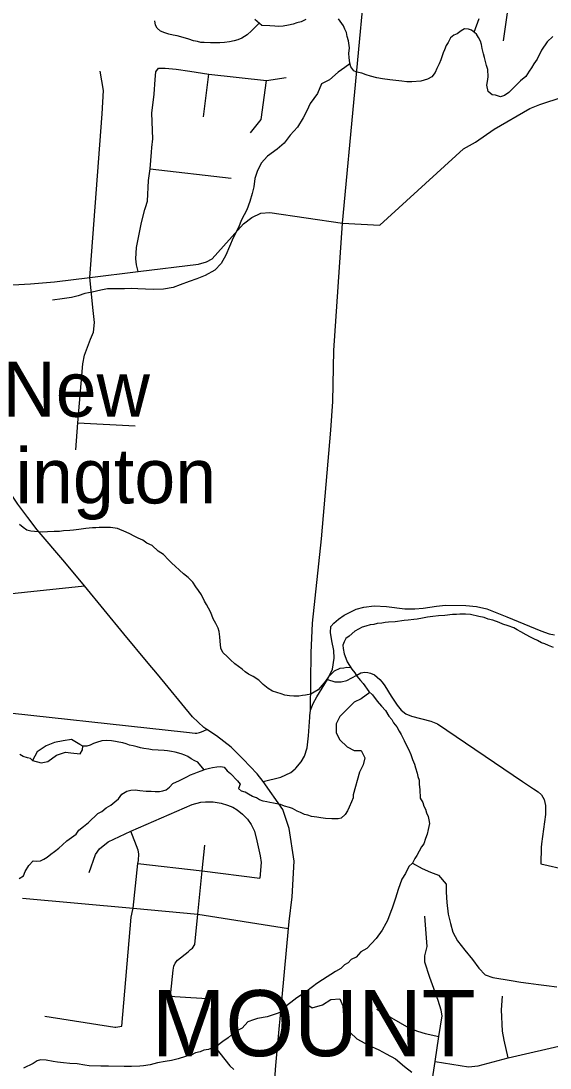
# Model space of a CAD drawing. Extents: x 0 to 34, y 0 to 22.
# Drawn here: x 6.214 to 6.973, y 17.057 to 18.558 of the extents above; entities that cross this region are included whole.
import ezdxf

# ---------------------------------------------------------------- set-up
doc = ezdxf.new("R2010")
doc.units = 0
for name, color, linetype in [('GM_X_Corporation_Text', 7, 'Continuous'), ('GM_X_County_Road', 7, 'Continuous'), ('GM_X_Minor_Lake', 7, 'Continuous'), ('GM_X_Minor_River', 7, 'Continuous'), ('GM_X_Township_Subdivision', 7, 'Continuous'), ('GM_X_Unincorporated_Text', 7, 'Continuous'), ('GM_X_US_Route', 7, 'Continuous')]:
    doc.layers.add(name, color=color, linetype=linetype)

msp = doc.modelspace()

# ---------------------------------------------------------------- linework, layer by layer
at = {"layer": 'GM_X_County_Road'}
for points in [[(6.6289, 17.5702), (6.6299, 17.6523), (6.6319, 17.6948), (6.6451, 17.8156), (6.6585, 17.9713), (6.6613, 18.0126), (6.6624, 18.0856), (6.6748, 18.2683), (6.7103, 18.6453), (6.7239, 18.8027), (6.734, 18.8917), (6.7405, 19.0079)], [(6.6748, 18.2683), (6.7285, 18.2655), (6.8486, 18.3747), (6.8655, 18.3843), (6.8923, 18.4031), (6.9436, 18.4327), (6.9578, 18.4383), (6.9913, 18.4492), (7.0954, 18.4834), (7.0971, 18.484)], [(6.063, 18.1333), (6.1136, 18.1511), (6.1283, 18.1584), (6.17, 18.1715), (6.2024, 18.1796), (6.2275, 18.1814), (6.2621, 18.1839), (6.3129, 18.1902), (6.3819, 18.1988), (6.4683, 18.2096), (6.4798, 18.2126), (6.4879, 18.217), (6.533, 18.2673), (6.545, 18.2764), (6.5577, 18.2825), (6.5706, 18.2836), (6.6748, 18.2683)], [(6.6282, 17.5603), (6.6283, 17.5621), (6.6289, 17.5702), (6.633, 17.5796), (6.6382, 17.5893), (6.6534, 17.6142), (6.6608, 17.6291), (6.663, 17.6446), (6.6626, 17.6559), (6.6596, 17.6696), (6.6576, 17.6814), (6.6584, 17.6899), (6.6626, 17.695), (6.6695, 17.7008), (6.6773, 17.7062), (6.6946, 17.7151), (6.7055, 17.7177), (6.7206, 17.7197), (6.738, 17.7187), (6.7642, 17.7153), (6.7787, 17.7154), (6.7909, 17.7162), (6.81, 17.7191), (6.8227, 17.7208), (6.8517, 17.7202), (6.8672, 17.7188), (6.8821, 17.7156), (6.8941, 17.7107), (6.9106, 17.7038), (6.9593, 17.6839), (6.9714, 17.6796), (6.9791, 17.6783)], [(5.5312, 17.5084), (5.5691, 17.507), (5.6976, 17.4979), (5.7449, 17.494), (5.7812, 17.4914), (5.8077, 17.4899), (5.8238, 17.4905), (5.8392, 17.4936), (5.8617, 17.5004), (5.9034, 17.5131), (5.9959, 17.5435), (6.0061, 17.5479), (6.0184, 17.5562), (6.041, 17.5742), (6.0478, 17.5777), (6.0541, 17.5801), (6.0612, 17.5813), (6.0695, 17.5816), (6.1446, 17.5721), (6.4513, 17.5386)], [(6.607, 17.486), (6.6073, 17.4862), (6.6082, 17.4869), (6.6157, 17.4962), (6.6204, 17.504), (6.6242, 17.5161), (6.6263, 17.5335), (6.6282, 17.5603)], [(6.4513, 17.5386), (6.4638, 17.5372), (6.4661, 17.5373), (6.47, 17.538), (6.4727, 17.5389), (6.4763, 17.5404), (6.4804, 17.5426)], [(6.5612, 17.4679), (6.5866, 17.4743), (6.6008, 17.481), (6.607, 17.486)]]:
    msp.add_lwpolyline(points, dxfattribs=at)
at = {"layer": 'GM_X_Minor_Lake'}
for points in [[(6.3028, 17.5185), (6.2984, 17.5211), (6.2864, 17.5282), (6.2746, 17.5262), (6.262, 17.5238), (6.2501, 17.5191), (6.237, 17.5106), (6.2303, 17.4982), (6.2428, 17.4945), (6.2523, 17.4966), (6.2651, 17.5058)], [(6.2651, 17.5058), (6.2777, 17.5098), (6.2857, 17.5092), (6.2989, 17.5074), (6.3021, 17.5134), (6.3028, 17.5185)]]:
    msp.add_lwpolyline(points, dxfattribs=at)
at = {"layer": 'GM_X_Minor_River'}
for points in [[(6.5554, 18.5548), (6.5443, 18.5441), (6.5385, 18.5381), (6.5308, 18.5333), (6.5251, 18.5311), (6.5197, 18.5294), (6.5132, 18.5283), (6.506, 18.5273), (6.4992, 18.5267), (6.4946, 18.5268), (6.4859, 18.5266), (6.4768, 18.5272), (6.4718, 18.5273), (6.4669, 18.5285), (6.4613, 18.5298), (6.4549, 18.5318), (6.45, 18.5334), (6.4379, 18.5367), (6.4322, 18.5376), (6.4258, 18.5392), (6.4201, 18.5412), (6.4141, 18.5433), (6.4092, 18.5475), (6.4071, 18.5521), (6.4057, 18.5583)], [(6.6224, 18.56), (6.6155, 18.5567), (6.6094, 18.5553), (6.6045, 18.5535), (6.5976, 18.5521), (6.59, 18.5508), (6.5835, 18.5501), (6.5782, 18.5506), (6.5706, 18.5512), (6.5593, 18.5514), (6.5492, 18.5603)], [(6.8077, 18.4844), (6.803, 18.478), (6.7968, 18.4744), (6.7873, 18.4719), (6.7744, 18.471), (6.7672, 18.4708), (6.7603, 18.4717), (6.7513, 18.4726), (6.7429, 18.4735), (6.7323, 18.4749), (6.724, 18.4766), (6.7153, 18.4787), (6.7089, 18.4807), (6.7025, 18.4831), (6.6957, 18.4848), (6.6912, 18.4867), (6.6871, 18.4925), (6.6853, 18.4975), (6.6844, 18.5059), (6.6841, 18.5112), (6.685, 18.5196), (6.6837, 18.5295), (6.6816, 18.5356), (6.6805, 18.5417), (6.6784, 18.5463), (6.6762, 18.5513), (6.6692, 18.561)], [(6.8636, 18.5422), (6.8711, 18.5615)], [(6.9765, 18.5358), (6.9684, 18.528), (6.9602, 18.516), (6.9542, 18.5032), (6.9495, 18.4968), (6.946, 18.4911), (6.9425, 18.4859), (6.9378, 18.4784), (6.9304, 18.4724), (6.9219, 18.4642), (6.9134, 18.4553), (6.9072, 18.4512), (6.9015, 18.4491), (6.8943, 18.4515), (6.8898, 18.4523), (6.8838, 18.457), (6.8821, 18.4658), (6.8829, 18.4711), (6.8838, 18.4779), (6.8833, 18.4886), (6.8815, 18.4943), (6.8787, 18.5058), (6.8773, 18.5108), (6.8752, 18.5184), (6.8742, 18.5242), (6.8727, 18.5291), (6.8698, 18.5345), (6.8672, 18.5391), (6.8601, 18.545), (6.8556, 18.5462), (6.8499, 18.5467), (6.8453, 18.5438), (6.8392, 18.5397), (6.8346, 18.5375), (6.8299, 18.5338), (6.8264, 18.5274), (6.8236, 18.5229), (6.8212, 18.5169), (6.8192, 18.5123), (6.816, 18.5025), (6.8136, 18.4968), (6.8104, 18.4897), (6.8077, 18.4844)], [(6.6856, 18.4968), (6.6785, 18.4915), (6.6689, 18.4845), (6.6565, 18.4737), (6.645, 18.4678), (6.639, 18.4543), (6.6288, 18.4397), (6.6237, 18.4291), (6.6185, 18.419), (6.6103, 18.4059), (6.6002, 18.3943), (6.5916, 18.3827), (6.5812, 18.3745), (6.5676, 18.3642), (6.5583, 18.3541), (6.5528, 18.3424), (6.5491, 18.3322), (6.5481, 18.3205), (6.5456, 18.3107), (6.542, 18.2993), (6.5379, 18.2873), (6.5304, 18.273), (6.526, 18.262), (6.5181, 18.247), (6.5129, 18.2349), (6.5077, 18.2225), (6.501, 18.2105), (6.4921, 18.2008), (6.4779, 18.1931), (6.466, 18.1884), (6.4553, 18.1844), (6.4423, 18.1798), (6.4323, 18.1762), (6.4182, 18.1738), (6.4038, 18.1733), (6.3924, 18.1736), (6.3814, 18.1742), (6.3719, 18.1747), (6.3624, 18.1742), (6.3513, 18.174), (6.338, 18.1739), (6.3285, 18.1722), (6.3159, 18.1694), (6.3056, 18.1674), (6.296, 18.1641), (6.2865, 18.1617), (6.2732, 18.16), (6.2594, 18.1577)], [(6.6867, 17.6307), (6.6814, 17.6312), (6.6768, 17.6305), (6.6711, 17.6299), (6.6631, 17.6262), (6.6549, 17.618), (6.6506, 17.6116), (6.646, 17.606), (6.6401, 17.5993), (6.6344, 17.596), (6.6298, 17.593), (6.6221, 17.5917), (6.6176, 17.591), (6.6126, 17.5903), (6.6054, 17.5901), (6.599, 17.5906), (6.5922, 17.5919), (6.5873, 17.5935), (6.5744, 17.5976), (6.5684, 17.6011), (6.5613, 17.6069), (6.555, 17.6132), (6.5468, 17.6183), (6.5404, 17.6218), (6.5355, 17.6253), (6.531, 17.6289), (6.5206, 17.6367), (6.5146, 17.6421), (6.5101, 17.6464), (6.5034, 17.653), (6.5005, 17.6591), (6.4996, 17.669), (6.499, 17.6755), (6.498, 17.6828), (6.4969, 17.6877), (6.4933, 17.6946), (6.4896, 17.7012), (6.486, 17.71), (6.4831, 17.7162), (6.4802, 17.7215), (6.4772, 17.7265), (6.4728, 17.7354), (6.4684, 17.7415), (6.4647, 17.7469), (6.4603, 17.7535), (6.4536, 17.7601), (6.4469, 17.7656), (6.4413, 17.771), (6.4353, 17.7764), (6.4301, 17.7811), (6.4253, 17.7858), (6.4182, 17.7935), (6.4107, 17.7979), (6.4022, 17.8064), (6.3943, 17.8096), (6.3887, 17.8139), (6.3819, 17.8167), (6.3762, 17.8198), (6.3702, 17.823), (6.365, 17.8254), (6.3526, 17.8306), (6.3423, 17.8319), (6.3359, 17.8321), (6.326, 17.8319), (6.3214, 17.8316), (6.3165, 17.8313), (6.307, 17.8304), (6.2971, 17.829), (6.2891, 17.8284), (6.2842, 17.8278), (6.275, 17.8272), (6.2693, 17.8265), (6.2617, 17.8263), (6.2519, 17.8257), (6.2443, 17.8255), (6.239, 17.8256), (6.2333, 17.8261), (6.228, 17.8266), (6.2223, 17.8282), (6.2171, 17.8318), (6.2118, 17.8364)], [(6.9777, 17.6602), (6.9702, 17.663), (6.9653, 17.6654), (6.9604, 17.6667), (6.9547, 17.6698), (6.9491, 17.6726), (6.9446, 17.6746), (6.9382, 17.6781), (6.9307, 17.6825), (6.9254, 17.6852), (6.9206, 17.688), (6.9127, 17.6912), (6.9051, 17.6936), (6.8995, 17.696), (6.8904, 17.6992), (6.884, 17.7005), (6.878, 17.7029), (6.8704, 17.7046), (6.8583, 17.7071), (6.8515, 17.7076), (6.8432, 17.7078), (6.8386, 17.7075), (6.8329, 17.7072), (6.8219, 17.7059), (6.8127, 17.7054), (6.8044, 17.7044), (6.7968, 17.7034), (6.7895, 17.702), (6.7819, 17.7007), (6.7773, 17.7), (6.7693, 17.699), (6.7636, 17.6987), (6.7507, 17.6967), (6.7408, 17.6962), (6.7362, 17.6959), (6.7313, 17.6948), (6.7248, 17.6942), (6.7199, 17.6932), (6.7145, 17.6925), (6.7084, 17.6907), (6.7031, 17.6893), (6.6927, 17.6834), (6.6846, 17.6764), (6.68, 17.673), (6.6776, 17.6681), (6.6756, 17.6632), (6.6759, 17.6587), (6.6773, 17.651), (6.6798, 17.6449), (6.6816, 17.6395), (6.6882, 17.6287), (6.6926, 17.6237), (6.6956, 17.6191), (6.7008, 17.6129), (6.7045, 17.6083), (6.7126, 17.5971), (6.7178, 17.592), (6.7248, 17.5831), (6.7311, 17.5758), (6.7367, 17.5696), (6.7415, 17.5615), (6.7456, 17.5569), (6.7481, 17.5522), (6.7529, 17.5461), (6.7562, 17.5399), (6.7592, 17.5353), (6.7632, 17.5265), (6.7661, 17.5207), (6.7694, 17.5145), (6.773, 17.5065), (6.7755, 17.4996), (6.778, 17.4927), (6.7798, 17.4873), (6.782, 17.4797), (6.783, 17.4751), (6.7848, 17.4697), (6.7851, 17.4636), (6.786, 17.4564)], [(6.714, 17.5957), (6.702, 17.5866), (6.6918, 17.5815), (6.6713, 17.561), (6.6661, 17.5507), (6.6661, 17.5379), (6.6713, 17.5276), (6.6815, 17.5174), (6.6918, 17.5122), (6.702, 17.5122), (6.7072, 17.502), (6.7046, 17.4917), (6.6995, 17.4814), (6.6902, 17.449)], [(6.4765, 17.4848), (6.4676, 17.4955), (6.4631, 17.4975), (6.4578, 17.5006), (6.4533, 17.5038), (6.4488, 17.5057), (6.4435, 17.5074), (6.4349, 17.5098), (6.4299, 17.5107), (6.4239, 17.5119), (6.4194, 17.5124), (6.4106, 17.513), (6.4023, 17.5135), (6.3974, 17.5144), (6.3902, 17.5153), (6.3853, 17.5161), (6.3804, 17.5178), (6.3747, 17.519), (6.3698, 17.5199), (6.3649, 17.5219), (6.36, 17.5235), (6.3543, 17.5244), (6.3494, 17.5252), (6.3437, 17.5261), (6.3369, 17.5266), (6.3297, 17.5264), (6.3224, 17.5239), (6.3178, 17.5224), (6.3132, 17.5202), (6.3083, 17.5188), (6.3033, 17.5185), (6.3028, 17.5185)], [(6.2303, 17.4982), (6.2278, 17.501), (6.2233, 17.5019), (6.2172, 17.5039), (6.2124, 17.5067)], [(6.4317, 17.465), (6.4413, 17.4694), (6.4462, 17.4716), (6.452, 17.4745), (6.457, 17.4774), (6.4623, 17.4792), (6.4669, 17.4814), (6.4723, 17.4832), (6.4788, 17.4857), (6.4841, 17.4868), (6.4887, 17.4882), (6.4948, 17.4889), (6.5005, 17.4895), (6.5054, 17.4883), (6.5095, 17.4832), (6.5143, 17.4793), (6.5244, 17.4689), (6.5285, 17.4642), (6.5258, 17.4578)], [(6.786, 17.4564), (6.7863, 17.444), (6.7903, 17.4378), (6.7917, 17.4328), (6.7942, 17.4282), (6.7956, 17.4232), (6.7977, 17.4178), (6.7987, 17.4128), (6.7997, 17.4075), (6.798, 17.3992), (6.7963, 17.3924), (6.7938, 17.3863), (6.7914, 17.3788), (6.7882, 17.3743), (6.7814, 17.3619), (6.7786, 17.3574), (6.7754, 17.3507), (6.7699, 17.3462), (6.7651, 17.3361), (6.7603, 17.3279), (6.7546, 17.3132), (6.7512, 17.3007), (6.7463, 17.2864), (6.7442, 17.2815), (6.7393, 17.2687), (6.7369, 17.2642), (6.7317, 17.2548), (6.7234, 17.2428), (6.7097, 17.2287), (6.7012, 17.2236), (6.6945, 17.2162), (6.6876, 17.2126), (6.6829, 17.2082), (6.6779, 17.2053), (6.6728, 17.1997), (6.6651, 17.1957), (6.6465, 17.1837), (6.6384, 17.1782), (6.6318, 17.1734), (6.6221, 17.1661), (6.6097, 17.158), (6.605, 17.1544), (6.5949, 17.1463), (6.5898, 17.1392), (6.5828, 17.1359), (6.5771, 17.1338), (6.5671, 17.1307), (6.553, 17.1284), (6.5476, 17.1263), (6.5391, 17.1235), (6.5313, 17.1145), (6.5201, 17.1088), (6.5111, 17.1006), (6.5034, 17.0951), (6.4952, 17.0889), (6.4829, 17.0839), (6.4764, 17.0829), (6.471, 17.0804), (6.4642, 17.0791), (6.458, 17.0758), (6.45, 17.0738), (6.4392, 17.0703), (6.43, 17.0682), (6.4209, 17.0666), (6.4098, 17.0646), (6.399, 17.0619), (6.3899, 17.0606), (6.3842, 17.06), (6.3727, 17.0596), (6.3621, 17.0595), (6.3393, 17.0601), (6.3283, 17.06), (6.3119, 17.0605), (6.3055, 17.0614), (6.2945, 17.0633), (6.2839, 17.0639), (6.2748, 17.0646), (6.2664, 17.0656), (6.26, 17.0665), (6.2502, 17.0683), (6.2422, 17.0689), (6.2372, 17.0675), (6.2314, 17.0635), (6.2175, 17.057)], [(6.2866, 17.3876), (6.2932, 17.3923), (6.2971, 17.3983), (6.3037, 17.4034), (6.3107, 17.409), (6.3244, 17.4219), (6.3298, 17.4248), (6.336, 17.4303), (6.3426, 17.434), (6.3488, 17.4387), (6.3539, 17.4432), (6.3586, 17.4499), (6.366, 17.4543), (6.3717, 17.4556), (6.3778, 17.4558), (6.3842, 17.4549), (6.3937, 17.4542), (6.4009, 17.454), (6.4066, 17.4535), (6.4127, 17.4537), (6.4173, 17.4544), (6.4223, 17.4561), (6.427, 17.4598), (6.4317, 17.465)], [(6.6902, 17.449), (6.6901, 17.4444), (6.688, 17.4388), (6.6844, 17.4313), (6.682, 17.426), (6.6788, 17.4204), (6.6733, 17.4156), (6.6687, 17.4142), (6.6596, 17.4144), (6.6505, 17.4151), (6.6437, 17.4157), (6.638, 17.4166), (6.6304, 17.4179), (6.6251, 17.4196), (6.6206, 17.4205), (6.615, 17.4237), (6.6101, 17.4254), (6.6033, 17.429), (6.5988, 17.4306), (6.5917, 17.4327), (6.586, 17.4348), (6.5807, 17.4361), (6.5762, 17.437), (6.5709, 17.4379), (6.5663, 17.4388), (6.5614, 17.4397), (6.5562, 17.4417), (6.5517, 17.4445), (6.546, 17.4462), (6.54, 17.4498), (6.5355, 17.4526), (6.5303, 17.4542), (6.5258, 17.4578)], [(6.2116, 17.3291), (6.2174, 17.3327), (6.2202, 17.3391), (6.2254, 17.3477), (6.2317, 17.354), (6.2362, 17.3539), (6.2419, 17.3541), (6.247, 17.3567), (6.2516, 17.3596), (6.257, 17.364), (6.2621, 17.3677), (6.2683, 17.3724), (6.2734, 17.3773), (6.2796, 17.3828), (6.2866, 17.3876)], [(6.7756, 17.3511), (6.789, 17.3433), (6.8011, 17.3378), (6.8128, 17.3337), (6.8235, 17.3206), (6.8236, 17.3095), (6.8245, 17.2947), (6.8267, 17.2779), (6.8299, 17.2646), (6.8334, 17.252), (6.84, 17.2397), (6.8503, 17.2261), (6.8614, 17.2126), (6.8703, 17.2003), (6.8795, 17.1906), (6.8905, 17.1869), (6.917, 17.1825), (6.9306, 17.1803), (6.9416, 17.179), (6.956, 17.1771), (6.9674, 17.1757), (6.9821, 17.1735)], [(6.6154, 17.1618), (6.6219, 17.1502), (6.6316, 17.1435), (6.6461, 17.1477), (6.6581, 17.1555), (6.671, 17.1563), (6.6753, 17.1464), (6.6766, 17.1326), (6.6804, 17.1189), (6.6859, 17.1081), (6.6956, 17.0992), (6.7121, 17.0901), (6.7272, 17.0833), (6.7377, 17.0774), (6.7512, 17.0706), (6.7639, 17.0593), (6.7743, 17.0511)], [(6.4918, 17.0875), (6.5135, 17.0602), (6.519, 17.0551)]]:
    msp.add_lwpolyline(points, dxfattribs=at)
at = {"layer": 'GM_X_Township_Subdivision'}
for points in [[(6.9555, 18.8557), (6.9347, 18.639), (6.9257, 18.6167), (6.9157, 18.6034), (6.9052, 18.5296)], [(6.3138, 18.2028), (6.3304, 18.425), (6.3322, 18.4584), (6.3274, 18.4859)], [(6.4018, 18.3765), (6.403, 18.3892), (6.4017, 18.4257), (6.4051, 18.4532), (6.4066, 18.4741), (6.4072, 18.4851), (6.4112, 18.4906), (6.4207, 18.4906), (6.4366, 18.4888), (6.4562, 18.4863), (6.4832, 18.4817), (6.5659, 18.4725), (6.5944, 18.4771)], [(6.4758, 18.4205), (6.4832, 18.4817)], [(6.5429, 18.3975), (6.5583, 18.4168), (6.5659, 18.4725)], [(6.3944, 18.2969), (6.3953, 18.2999), (6.397, 18.3293), (6.3991, 18.3459), (6.4013, 18.3699), (6.4018, 18.3765)], [(6.3991, 18.3459), (6.5156, 18.3328)], [(6.3819, 18.1988), (6.3795, 18.2083), (6.3787, 18.2169), (6.3795, 18.2334), (6.3866, 18.2693), (6.3915, 18.2879), (6.3933, 18.2934), (6.3944, 18.2969)], [(6.2927, 17.9432), (6.2957, 17.9819), (6.3025, 18.0664), (6.3051, 18.0789), (6.3138, 18.1018), (6.3179, 18.1119), (6.3194, 18.1259), (6.3177, 18.1431), (6.3129, 18.1902), (6.3138, 18.2028), (6.3138, 18.2028)], [(6.2957, 17.9819), (6.3778, 17.9775)], [(6.022, 17.7199), (6.0333, 17.7203), (6.0558, 17.7219), (6.305, 17.7484)], [(6.6534, 17.6142), (6.6641, 17.611), (6.6733, 17.6109), (6.6812, 17.6129), (6.6957, 17.6204), (6.7014, 17.6238), (6.707, 17.6247), (6.7113, 17.6242), (6.7153, 17.6231), (6.7208, 17.6209), (6.7249, 17.6176), (6.7287, 17.6142), (6.7318, 17.6105), (6.7357, 17.6052), (6.7448, 17.5901), (6.7534, 17.5774), (6.7593, 17.5701), (6.7657, 17.5649), (6.774, 17.5616), (6.8017, 17.5545), (6.811, 17.5506), (6.9333, 17.468), (6.949, 17.4576), (6.9557, 17.4533), (6.9602, 17.4488), (6.9641, 17.4423), (6.966, 17.4334), (6.9663, 17.4208), (6.9605, 17.3786)], [(6.3116, 17.3375), (6.3208, 17.3633), (6.3268, 17.3712), (6.3389, 17.3814), (6.3713, 17.3969), (6.4596, 17.4348), (6.4721, 17.4381), (6.4784, 17.4387), (6.4894, 17.4388), (6.5012, 17.4371), (6.5103, 17.4341), (6.5176, 17.431), (6.5239, 17.4271), (6.5317, 17.4211), (6.539, 17.4137), (6.5439, 17.4061), (6.5488, 17.3969), (6.5523, 17.3829), (6.557, 17.3613), (6.5583, 17.3518), (6.5565, 17.3292)], [(6.3742, 17.2843), (6.3747, 17.2864), (6.3817, 17.3502), (6.3823, 17.3546), (6.383, 17.3642), (6.3822, 17.3696), (6.3713, 17.3969)], [(6.4887, 17.1557), (6.4348, 17.1593), (6.4308, 17.1599), (6.4289, 17.1618), (6.4287, 17.1653), (6.432, 17.1977), (6.4331, 17.2031), (6.4351, 17.2074), (6.4382, 17.2119), (6.4537, 17.2239), (6.4572, 17.2269), (6.4598, 17.2292), (6.4634, 17.2344), (6.4676, 17.2776), (6.4737, 17.3397), (6.4774, 17.3767)], [(6.9605, 17.3786), (6.9598, 17.3731), (6.9592, 17.3497)], [(6.3817, 17.3502), (6.4737, 17.3397), (6.5565, 17.3292)], [(6.9592, 17.3497), (6.997, 17.3415), (7.0662, 17.3297), (7.0999, 17.3233)], [(6.216, 17.3009), (6.3747, 17.2864), (6.4676, 17.2776), (6.5974, 17.257)], [(6.3586, 17.1174), (6.3719, 17.2737), (6.3742, 17.2843)], [(6.7844, 16.9112), (6.7902, 16.9495), (6.799, 17.0076), (6.8079, 17.0668), (6.8133, 17.1023), (6.8178, 17.1319), (6.8167, 17.1402), (6.8123, 17.154), (6.8001, 17.1868), (6.7932, 17.2092), (6.7932, 17.218), (6.7964, 17.2316), (6.7931, 17.275)], [(6.9126, 17.0718), (6.9066, 17.0971), (6.9044, 17.1101), (6.9031, 17.1405), (6.9045, 17.1601)], [(6.7238, 17.1416), (6.7702, 17.1147), (6.7826, 17.11), (6.7935, 17.1067), (6.8133, 17.1023)], [(6.2483, 17.1314), (6.3486, 17.116)], [(6.8079, 17.0668), (6.8559, 17.059), (6.8697, 17.0604), (6.9126, 17.0718), (6.9976, 17.0915), (7.0535, 17.1074), (7.0787, 17.1167), (7.0879, 17.1194), (7.1083, 17.126), (7.1159, 17.1268), (7.1214, 17.127), (7.1302, 17.1268), (7.1611, 17.1219), (7.2871, 17.0984), (7.3191, 17.0935)], [(6.3486, 17.116), (6.3502, 17.1157), (6.3586, 17.1174)]]:
    msp.add_lwpolyline(points, dxfattribs=at)
at = {"layer": 'GM_X_US_Route'}
for points in [[(6.3964, 17.6376), (6.3615, 17.6796), (6.305, 17.7484), (6.277, 17.7824), (6.2372, 17.8287), (6.224, 17.8461), (6.2093, 17.8655), (6.1706, 17.9227), (6.1378, 17.9744), (6.1043, 18.0396)], [(6.5857, 17.1275), (6.5974, 17.257), (6.5985, 17.2671), (6.6027, 17.3024), (6.6056, 17.3535), (6.5985, 17.4006), (6.5894, 17.4276), (6.5612, 17.4679), (6.5528, 17.4791), (6.5325, 17.4997), (6.5155, 17.5173), (6.4943, 17.5334), (6.4804, 17.5426), (6.4764, 17.5452), (6.4601, 17.5608), (6.4096, 17.6217), (6.3964, 17.6376)], [(6.5713, 16.9682), (6.5773, 17.0352), (6.5796, 17.0608), (6.5848, 17.1183), (6.5857, 17.1275)]]:
    msp.add_lwpolyline(points, dxfattribs=at)

# ---------------------------------------------------------------- texts
at = {"layer": 'GM_X_Corporation_Text'}
msp.add_text('MOUNT', height=0.0947, rotation=0, dxfattribs=at).set_placement((6.4017, 17.0742))
at = {"layer": 'GM_X_Unincorporated_Text'}
for s, p in [('New', (6.1875, 17.9907)), ('Burlington', (6.0184, 17.8665))]:
    msp.add_text(s, height=0.07898, rotation=0, dxfattribs=at).set_placement(p)

doc.saveas('drawing.dxf')
